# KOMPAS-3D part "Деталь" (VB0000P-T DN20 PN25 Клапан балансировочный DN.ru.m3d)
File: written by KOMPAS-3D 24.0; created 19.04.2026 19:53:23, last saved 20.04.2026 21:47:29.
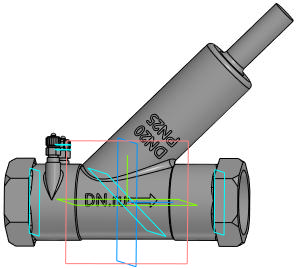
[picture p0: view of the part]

Document properties: Автор: mrdid; Полное имя файла: C:\Работа\VB0000P-T DN X PN 25 Клапан балансировочный DN.ru\DN20\исходные материалы\VB0000P-T DN20 PN25 Клапан балансировочный DN.ru.m3d

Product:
- Part/product: Деталь
    Масса: 0.513247

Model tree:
1. Эскиз:1
2. Элемент вращения:1
     Угол 1 = 360
3. Фаска:1  (with: Ребро.Элемент вращения:1)
     Угол = 45; Длина 1 = 3; Длина 2 = 3
4. Фаска:2  (with: Ребро.Элемент вращения:1)
     Угол = 45; Длина 1 = 2; Длина 2 = 2
5. Фаска:3  (with: Ребро.Элемент вращения:1)
     Угол = 45; Длина 1 = 1; Длина 2 = 1
6. Фаска:4  (with: Ребро.Элемент вращения:1)
     Угол = 30; Длина 1 = 3; Длина 2 = 1.73205
7. Смещенная плоскость:1  (with: Грань.Элемент вращения:1)
     Расстояние = 10
8. Эскиз:2
9. Элемент выдавливания:1  (with: Грань.Фаска:4)
     Расстояние 1 = 38.558
10. Эскиз:3
11. Элемент выдавливания:2  (with: Грань.Фаска:4)
     Расстояние 2 = 18.7873
12. Смещенная плоскость:2  (with: Грань.Элемент вращения:1)
     Расстояние = 10
13. Эскиз:4  (with: Ребро.Фаска:4)
14. Элемент выдавливания:3  (with: Грань.Фаска:4)
     Расстояние 2 = 38.558
15. Эскиз:5
16. Элемент выдавливания:4  (with: Грань.Фаска:4)
     Расстояние 2 = 48.558
17. Фаска:5  (with: Ребро.Элемент выдавливания:4)
     Угол = 45; Длина 1 = 2; Длина 2 = 2
18. Плоскость под углом:1
     Угол = 46
19. Касательная плоскость:1  (with: Грань.Элемент вращения:1)
20. Эскиз:6  (with: Ребро.Фаска:3)
21. Элемент выдавливания:5  (with: Грань.Элемент вращения:1)
     Расстояние 1 = -8.61666; Смещение 1 = -1; Расстояние 2 = 70
22. Эскиз:7  (with: Грань.Элемент вращения:1)
23. Элемент выдавливания:6  (with: Грань.Элемент вращения:1)
24. Эскиз:8  (with: Грань.Элемент выдавливания:6, Ребро.Элемент выдавливания:6)
25. Элемент выдавливания:7
     Расстояние 1 = 2
26. Эскиз:9  (with: Грань.Элемент выдавливания:7, Ребро.Элемент выдавливания:7)
27. Элемент выдавливания:8
     Расстояние 1 = 1
28. Эскиз:10  (with: Грань.Элемент выдавливания:8, Ребро.Элемент выдавливания:6)
29. Элемент выдавливания:10
     Расстояние 1 = 3
30. Эскиз:11  (with: Грань.Элемент выдавливания:10, Ребро.Элемент выдавливания:6)
31. Элемент выдавливания:11
     Расстояние 1 = 1
32. Эскиз:12  (with: Грань.Элемент выдавливания:11, Ребро.Элемент выдавливания:6)
33. Элемент выдавливания:12
     Расстояние 1 = 3
34. Эскиз:13  (with: Грань.Элемент выдавливания:12, Ребро.Элемент выдавливания:7)
35. Элемент выдавливания:13
     Расстояние 1 = 2
36. Скругление:1  (with: Ребро.Элемент выдавливания:13)
     Радиус = 1
37. Средняя плоскость:2  (with: Грань.Элемент выдавливания:12, Грань.Элемент выдавливания:10)
38. Эскиз:14  (with: Ребро.Элемент выдавливания:11)
39. Элемент выдавливания:14
     Расстояние 1 = 0.5
40. Средняя плоскость:3  (with: Грань.Элемент выдавливания:12)
41. Эскиз:15  (with: Вершина.Элемент выдавливания:14, Ребро.Элемент выдавливания:14)
42. Эскиз:16  (with: Грань.Элемент выдавливания:12, Ребро.Скругление:1)
43. Элемент выдавливания:15
     Расстояние 1 = 0.5
44. Элемент выдавливания:16  (with: Грань.Элемент выдавливания:15, Грань.Элемент выдавливания:14)
     Расстояние 1 = 1.5; Расстояние 2 = 1.75
45. Скругление:2  (with: Ребро.Элемент выдавливания:14, Ребро.Элемент выдавливания:15, Ребро.Элемент выдавливания:16)
     Радиус = 1
46. Зеркальный массив:1
47. Экземпляр ( 1 )
48. Экземпляр ( 2 )  (with: Элемент выдавливания:15, Элемент выдавливания:16, Элемент выдавливания:14, Скругление:2)
49. Скругление:3  (with: Ребро.Элемент выдавливания:5)
     Радиус = 2
50. Скругление:4  (with: Ребро.Элемент выдавливания:6)
     Радиус = 1
51. Эскиз:17  (with: Грань.Элемент выдавливания:5, Ребро.Элемент выдавливания:5)
52. Элемент выдавливания:17
     Расстояние 1 = 30
53. Скругление:5  (with: Ребро.Элемент выдавливания:17, Ребро.Элемент выдавливания:5)
     Радиус = 2
54. Скругление:6  (with: Ребро.Элемент выдавливания:2, Ребро.Элемент выдавливания:4)
     Радиус = 1
55. Эскиз:19  (with: Грань.Элемент выдавливания:5)
56. Элемент выдавливания:19  (with: Грань.Элемент выдавливания:5)
     Расстояние 1 = 12.5784; Смещение 1 = 0.2
57. Эскиз:20
58. Элемент выдавливания:20  (with: Грань.Элемент вращения:1)
     Расстояние 1 = 15.2; Смещение 1 = 0.2; Расстояние 2 = 15.2; Смещение 2 = 0.2
59. Эскиз:21
60. Элемент выдавливания:21  (with: Грань.Элемент вращения:1)
     Расстояние 1 = 15.1986; Смещение 1 = 0.2
61. Эскиз:22  (with: Ребро.Фаска:2)
62. Элемент выдавливания:22
     Расстояние 1 = 48; Расстояние 2 = 67.6679

Expressions: 1/2*25.4
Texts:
  Линейный размер с обрывом
  GOST 26.020 Pr3
  var3D
  Gn+T+5
  Dn+1
  Ds-1
  Ds-2
  Ds-4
